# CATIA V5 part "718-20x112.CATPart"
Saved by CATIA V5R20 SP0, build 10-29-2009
Part number: 718-20x112
Definition: NONE
Nomenclature: 718-20x112
Source: Unknown
Description: 718-20x112
Bounding box of the stored display mesh (mm): x 0 to 135, y -12.5 to 12.5, z -12.5 to 12.5
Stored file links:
  C:\Users\Utente\Desktop\IO LAVORO\3D X SITO CF\X SITO\718\718-20x112.CATPart

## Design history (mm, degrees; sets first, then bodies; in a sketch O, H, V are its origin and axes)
Body1 "718-20x112" (main body)
  Solid1: solid without history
